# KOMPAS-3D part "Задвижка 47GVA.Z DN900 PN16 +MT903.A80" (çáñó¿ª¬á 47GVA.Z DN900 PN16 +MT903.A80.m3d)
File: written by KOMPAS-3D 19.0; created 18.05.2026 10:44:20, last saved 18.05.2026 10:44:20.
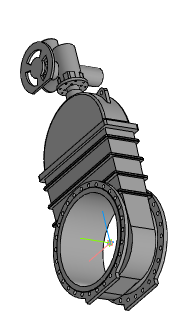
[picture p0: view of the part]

Document properties: Автор: Энергия; Полное имя файла: ..\Задвижка 47GVA.Z DN350_DN1200+MT903.A\Задвижка 47GVA.Z DN900 PN16 +MT903.A80.a3d

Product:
- Part/product: Задвижка 47GVA.Z DN900 PN16 +MT903.A80
    Масса: 3746.11
  - Body: Электропривод МТ903.А80 без блока управления
      Масса: 346.451
  - Body: Задвижка 47GVA.Z DN900 PN16 без исполнит. мех
      Масса: 3399.66

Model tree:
1. Операция без истории:1
2. Операция без истории:2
